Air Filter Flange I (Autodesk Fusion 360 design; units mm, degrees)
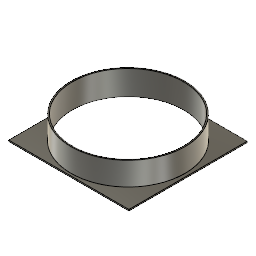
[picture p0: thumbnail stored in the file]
box_primitive "BoxPrimitive1" DistanceX 128 DistanceY 130 DistanceZ 1.5 OffsetDistanceX 0 OffsetDistanceY 0
cylinder_primitive "CylinderPrimitive1" Height 25 Diameter 123
hole "Hole1" HoleDepth 27 HoleDiameter 120 TipAngle 118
